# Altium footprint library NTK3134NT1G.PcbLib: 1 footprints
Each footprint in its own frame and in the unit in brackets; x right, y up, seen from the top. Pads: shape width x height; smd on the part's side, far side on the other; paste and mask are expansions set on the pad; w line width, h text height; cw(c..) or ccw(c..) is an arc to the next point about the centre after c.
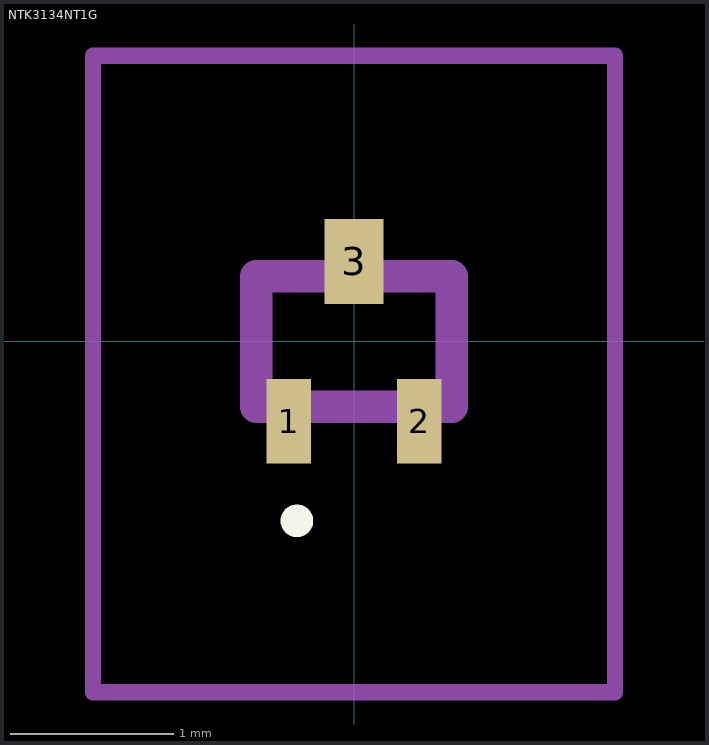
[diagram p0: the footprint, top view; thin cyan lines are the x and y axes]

## NTK3134NT1G [mm]
pads (3):
  rect 0.27x0.52 smd: 1(-0.4,-0.49) 2(0.4,-0.49)
  rect 0.36x0.52 smd: 3(0,0.49)
Top Overlay:
  lines w0.1: -0.4,-1.1 -0.4,-1.1 ; -0.4,-1.1 ccw(c-0.35,-1.1) -0.3,-1.1 ; -0.4,-1.1 cw(c-0.35,-1.1) -0.3,-1.1 ; -0.3,-1.1 -0.3,-1.1
Mechanical 15:
  lines w0.2: -0.6,-0.4 0.6,-0.4 0.6,0.4 -0.6,0.4 -0.6,-0.4
Mechanical 20:
  lines w0.1: -1.6,-2.15 1.6,-2.15 1.6,1.75 -1.6,1.75 -1.6,-2.15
